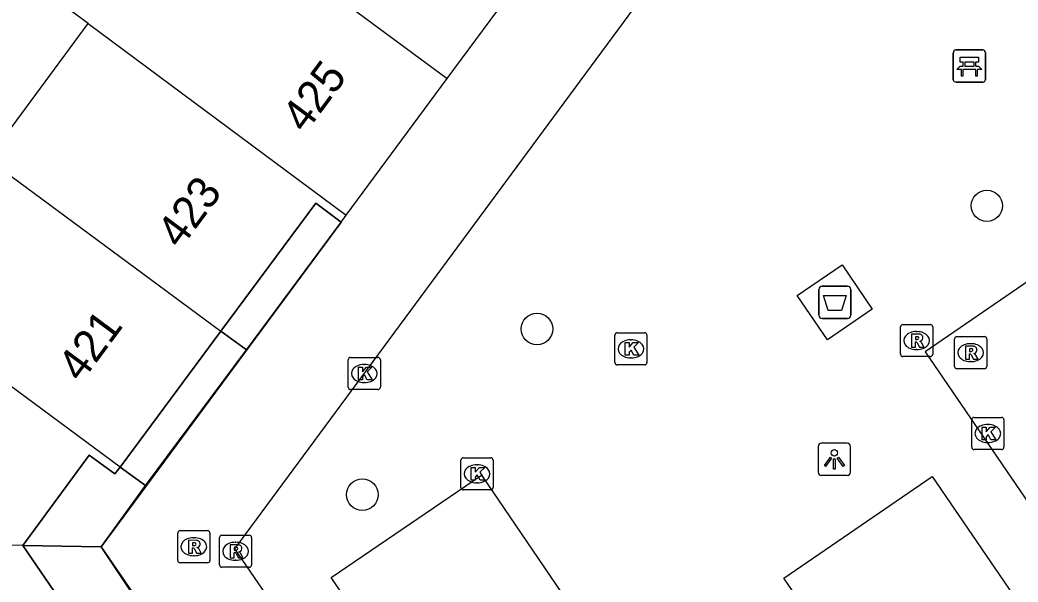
# Model space of a CAD drawing. Extents: x 155275 to 156263, y 382654 to 383635.
# Drawn here: x 155744.26 to 155775.32, y 383229.53 to 383247.02 of the extents above; entities that cross this region are included whole.
import ezdxf

# ---------------------------------------------------------------- set-up
doc = ezdxf.new("R2010")
doc.units = 0
for name, color, linetype in [('IMGEO_Afval_apart_plaats', 7, 'Continuous'), ('IMGEO_Bank', 7, 'Continuous'), ('IMGEO_Boom', 7, 'Continuous'), ('IMGEO_Kolk', 7, 'Continuous'), ('IMGEO_Lichtpunt', 7, 'Continuous'), ('IMGEO_Pand', 7, 'Continuous'), ('IMGEO_Pand_nummerreeks', 7, 'Continuous'), ('IMGEO_Pand_overbouw', 7, 'Continuous'), ('IMGEO_Rijbaan_lokaal_open', 7, 'Continuous'), ('IMGEO_Rioolput', 7, 'Continuous'), ('IMGEO_Voetpad_open', 7, 'Continuous')]:
    doc.layers.add(name, color=color, linetype=linetype)

msp = doc.modelspace()

# ---------------------------------------------------------------- linework, layer by layer
at = {"layer": 'IMGEO_Afval_apart_plaats'}
for p, q in [((155769.227, 383238.731), (155770.017, 383238.731)), ((155770.017, 383238.731), (155769.227, 383238.731)), ((155769.127, 383237.831), (155769.127, 383238.631)), ((155769.127, 383238.631), (155769.127, 383237.831)), ((155770.117, 383238.631), (155770.117, 383237.831)), ((155770.117, 383237.831), (155770.117, 383238.631)), ((155770.017, 383237.731), (155769.227, 383237.731)), ((155769.227, 383237.731), (155770.017, 383237.731))]:
    msp.add_line(p, q, dxfattribs=at)
msp.add_lwpolyline([(155769.27, 383238.445), (155769.974, 383238.445), (155769.825, 383237.975), (155769.419, 383237.975), (155769.27, 383238.445)], dxfattribs=at)
for centre, start, end in [((155769.227, 383238.631), 90, 180), ((155769.227, 383238.631), 90, 180), ((155770.017, 383238.631), 0, 90), ((155770.017, 383238.631), 360, 90), ((155769.227, 383237.831), 180, 270), ((155769.227, 383237.831), 180, 270), ((155770.017, 383237.831), 270, 0), ((155770.017, 383237.831), 270, 0)]:
    msp.add_arc(centre, 0.1, start, end, dxfattribs=at)
at = {"layer": 'IMGEO_Bank'}
for p, q in [((155773.31, 383245.157), (155773.31, 383245.998)), ((155773.31, 383245.998), (155773.31, 383245.157)), ((155773.385, 383246.082), (155774.226, 383246.082)), ((155774.226, 383246.082), (155773.385, 383246.082)), ((155774.31, 383246.007), (155774.31, 383245.166)), ((155774.31, 383245.166), (155774.31, 383246.007)), ((155773.619, 383245.588), (155773.619, 383245.694)), ((155773.663, 383245.694), (155773.663, 383245.588)), ((155773.951, 383245.7), (155773.669, 383245.7)), ((155773.669, 383245.582), (155773.951, 383245.582)), ((155773.957, 383245.588), (155773.957, 383245.694)), ((155774.001, 383245.694), (155774.001, 383245.588)), ((155774.007, 383245.48), (155773.614, 383245.48)), ((155774.235, 383245.082), (155773.394, 383245.082)), ((155773.394, 383245.082), (155774.235, 383245.082))]:
    msp.add_line(p, q, dxfattribs=at)
for points in [[(155773.557, 383245.48), (155773.415, 383245.48), (155773.527, 383245.582), (155773.613, 383245.582)], [(155773.613, 383245.7), (155773.527, 383245.7), (155773.527, 383245.861), (155774.09, 383245.861), (155774.09, 383245.7), (155774.007, 383245.7)], [(155774.007, 383245.582), (155774.09, 383245.582), (155774.202, 383245.48), (155774.063, 383245.48)], [(155773.607, 383245.473), (155773.607, 383245.266), (155773.564, 383245.266), (155773.564, 383245.473)], [(155774.057, 383245.473), (155774.057, 383245.266), (155774.013, 383245.266), (155774.013, 383245.473)]]:
    msp.add_lwpolyline(points, dxfattribs=at)
for centre, radius, start, end in [((155773.388, 383246.004), 0.0779, 92.4484, 184.2845), ((155773.388, 383246.004), 0.0779, 92.4484, 184.2845), ((155774.232, 383246.004), 0.0779, 2.4484, 94.2845), ((155774.232, 383246.004), 0.0779, 2.4484, 94.2845), ((155773.612, 383245.693), 0.00671, 2.8957, 87.1043), ((155773.612, 383245.589), 0.00671, 272.8957, 357.1043), ((155773.669, 383245.693), 0.00671, 92.8957, 177.1043), ((155773.669, 383245.589), 0.00671, 182.8957, 267.1043), ((155773.951, 383245.693), 0.00671, 2.8957, 87.1043), ((155773.951, 383245.589), 0.00671, 272.8957, 357.1043), ((155774.008, 383245.693), 0.00671, 92.8957, 177.1043), ((155774.008, 383245.589), 0.00671, 182.8957, 267.1043), ((155773.557, 383245.473), 0.00671, 2.8957, 87.1043), ((155773.614, 383245.473), 0.00671, 92.8957, 177.1043), ((155774.006, 383245.473), 0.00671, 2.8957, 87.1043), ((155774.063, 383245.473), 0.00671, 92.8957, 177.1043), ((155773.388, 383245.16), 0.0779, 182.4484, 274.2845), ((155773.388, 383245.16), 0.0779, 182.4484, 274.2845), ((155774.232, 383245.16), 0.0779, 272.4484, 4.2845), ((155774.232, 383245.16), 0.0779, 272.4484, 4.2845)]:
    msp.add_arc(centre, radius, start, end, dxfattribs=at)
at = {"layer": 'IMGEO_Boom'}
for centre in [(155774.353, 383241.234), (155760.353, 383237.403), (155754.919, 383232.248)]:
    msp.add_circle(centre, 0.489, dxfattribs=at)
at = {"layer": 'IMGEO_Kolk'}
for p, q in [((155762.775, 383236.358), (155762.775, 383237.21)), ((155762.85, 383237.284), (155763.702, 383237.284)), ((155763.776, 383237.21), (155763.776, 383236.358)), ((155763.263, 383237.064), (155763.288, 383237.064)), ((155754.479, 383235.591), (155754.479, 383236.443)), ((155754.554, 383236.517), (155755.406, 383236.517)), ((155754.967, 383236.297), (155754.992, 383236.297)), ((155755.48, 383236.443), (155755.48, 383235.591)), ((155763.702, 383236.284), (155762.85, 383236.284)), ((155763.286, 383236.504), (155763.261, 383236.504)), ((155754.99, 383235.737), (155754.965, 383235.737)), ((155755.406, 383235.517), (155754.554, 383235.517)), ((155773.883, 383233.725), (155773.883, 383234.577)), ((155773.958, 383234.651), (155774.81, 383234.651)), ((155774.371, 383234.431), (155774.396, 383234.431)), ((155774.884, 383234.577), (155774.884, 383233.725)), ((155774.394, 383233.871), (155774.369, 383233.871)), ((155774.81, 383233.651), (155773.958, 383233.651)), ((155757.988, 383232.471), (155757.988, 383233.323)), ((155758.063, 383233.397), (155758.915, 383233.397)), ((155758.476, 383233.177), (155758.501, 383233.177)), ((155758.989, 383233.323), (155758.989, 383232.471)), ((155758.499, 383232.617), (155758.474, 383232.617)), ((155758.915, 383232.397), (155758.063, 383232.397))]:
    msp.add_line(p, q, dxfattribs=at)
for points in [[(155762.775, 383236.358), (155762.775, 383237.21)], [(155762.85, 383237.284), (155763.702, 383237.284)], [(155763.776, 383237.21), (155763.776, 383236.358)], [(155763.096, 383236.984), (155763.219, 383236.984), (155763.219, 383236.833), (155763.349, 383236.984), (155763.513, 383236.984), (155763.367, 383236.833), (155763.52, 383236.584), (155763.368, 383236.584), (155763.283, 383236.748), (155763.219, 383236.681), (155763.219, 383236.584), (155763.096, 383236.584), (155763.096, 383236.984)], [(155754.479, 383235.591), (155754.479, 383236.443)], [(155754.554, 383236.517), (155755.406, 383236.517)], [(155755.48, 383236.443), (155755.48, 383235.591)], [(155763.702, 383236.284), (155762.85, 383236.284)], [(155754.8, 383236.217), (155754.923, 383236.217), (155754.923, 383236.066), (155755.053, 383236.217), (155755.217, 383236.217), (155755.071, 383236.066), (155755.224, 383235.817), (155755.072, 383235.817), (155754.987, 383235.981), (155754.923, 383235.914), (155754.923, 383235.817), (155754.8, 383235.817), (155754.8, 383236.217)], [(155755.406, 383235.517), (155754.554, 383235.517)], [(155773.883, 383233.725), (155773.883, 383234.577)], [(155773.958, 383234.651), (155774.81, 383234.651)], [(155774.884, 383234.577), (155774.884, 383233.725)], [(155774.204, 383234.351), (155774.327, 383234.351), (155774.327, 383234.2), (155774.457, 383234.351), (155774.621, 383234.351), (155774.475, 383234.2), (155774.628, 383233.951), (155774.476, 383233.951), (155774.391, 383234.115), (155774.327, 383234.048), (155774.327, 383233.951), (155774.204, 383233.951), (155774.204, 383234.351)], [(155774.81, 383233.651), (155773.958, 383233.651)], [(155757.988, 383232.471), (155757.988, 383233.323)], [(155758.063, 383233.397), (155758.915, 383233.397)], [(155758.989, 383233.323), (155758.989, 383232.471)], [(155758.309, 383233.097), (155758.432, 383233.097), (155758.432, 383232.946), (155758.562, 383233.097), (155758.726, 383233.097), (155758.58, 383232.946), (155758.733, 383232.697), (155758.581, 383232.697), (155758.496, 383232.861), (155758.432, 383232.794), (155758.432, 383232.697), (155758.309, 383232.697), (155758.309, 383233.097)], [(155758.915, 383232.397), (155758.063, 383232.397)]]:
    msp.add_lwpolyline(points, dxfattribs=at)
for centre, start, end in [((155762.852, 383237.208), 91.552, 178.448), ((155762.852, 383237.208), 91.552, 178.448), ((155763.7, 383237.208), 1.552, 88.448), ((155763.7, 383237.208), 1.552, 88.448), ((155754.556, 383236.441), 91.552, 178.448), ((155754.556, 383236.441), 91.552, 178.448), ((155755.404, 383236.441), 1.552, 88.448), ((155755.404, 383236.441), 1.552, 88.448), ((155762.852, 383236.36), 181.552, 268.448), ((155762.852, 383236.36), 181.552, 268.448), ((155763.7, 383236.36), 271.552, 358.448), ((155763.7, 383236.36), 271.552, 358.448), ((155754.556, 383235.593), 181.552, 268.448), ((155754.556, 383235.593), 181.552, 268.448), ((155755.404, 383235.593), 271.552, 358.448), ((155755.404, 383235.593), 271.552, 358.448), ((155773.96, 383234.575), 91.552, 178.448), ((155773.96, 383234.575), 91.552, 178.448), ((155774.808, 383234.575), 1.552, 88.448), ((155774.808, 383234.575), 1.552, 88.448), ((155773.96, 383233.727), 181.552, 268.448), ((155773.96, 383233.727), 181.552, 268.448), ((155774.808, 383233.727), 271.552, 358.448), ((155774.808, 383233.727), 271.552, 358.448), ((155758.065, 383233.321), 91.552, 178.448), ((155758.065, 383233.321), 91.552, 178.448), ((155758.913, 383233.321), 1.552, 88.448), ((155758.913, 383233.321), 1.552, 88.448), ((155758.065, 383232.473), 181.552, 268.448), ((155758.065, 383232.473), 181.552, 268.448), ((155758.913, 383232.473), 271.552, 358.448), ((155758.913, 383232.473), 271.552, 358.448)]:
    msp.add_arc(centre, 0.0765, start, end, dxfattribs=at)
for centre, major_axis, ratio, start_param, end_param in [((155763.262, 383236.784), (-0.387, 0.002), 0.722429, 4.712389, 7.853982), ((155763.287, 383236.784), (-0.39, 0.002), 0.717154, 1.570796, 4.712389), ((155754.966, 383236.017), (-0.387, 0.002), 0.722429, 4.712389, 7.853982), ((155754.991, 383236.017), (-0.39, 0.002), 0.717154, 1.570796, 4.712389), ((155774.37, 383234.151), (-0.387, 0.002), 0.722429, 4.712389, 7.853982), ((155774.395, 383234.151), (-0.39, 0.002), 0.717154, 1.570796, 4.712389), ((155758.475, 383232.897), (-0.387, 0.002), 0.722429, 4.712389, 7.853982), ((155758.5, 383232.897), (-0.39, 0.002), 0.717154, 1.570796, 4.712389)]:
    msp.add_ellipse(centre, major_axis=major_axis, ratio=ratio, start_param=start_param, end_param=end_param, dxfattribs=at)
at = {"layer": 'IMGEO_Lichtpunt'}
for p, q in [((155770.011, 383233.846), (155769.203, 383233.846)), ((155770.011, 383233.846), (155769.203, 383233.846)), ((155769.109, 383233.751), (155769.109, 383232.944)), ((155769.109, 383233.751), (155769.109, 383232.944)), ((155770.105, 383232.944), (155770.105, 383233.751)), ((155770.105, 383232.944), (155770.105, 383233.751)), ((155769.203, 383232.85), (155770.011, 383232.85)), ((155769.203, 383232.85), (155770.011, 383232.85))]:
    msp.add_line(p, q, dxfattribs=at)
for points in [[(155769.483, 383233.415), (155769.522, 383233.387), (155769.334, 383233.125), (155769.296, 383233.152), (155769.483, 383233.415)], [(155769.585, 383233.367), (155769.632, 383233.367), (155769.632, 383233.045), (155769.585, 383233.045), (155769.585, 383233.367)], [(155769.695, 383233.387), (155769.733, 383233.414), (155769.92, 383233.152), (155769.881, 383233.124), (155769.695, 383233.387)]]:
    msp.add_lwpolyline(points, dxfattribs=at)
msp.add_circle((155769.608, 383233.549), 0.0994, dxfattribs=at)
for centre, start, end in [((155769.203, 383233.751), 90, 180), ((155769.203, 383233.751), 90, 180), ((155770.011, 383233.751), 0, 90), ((155770.011, 383233.751), 0, 90), ((155769.203, 383232.944), 180, 270), ((155769.203, 383232.944), 180, 270), ((155770.011, 383232.944), 270, 0), ((155770.011, 383232.944), 270, 360)]:
    msp.add_arc(centre, 0.0946, start, end, dxfattribs=at)
at = {"layer": 'IMGEO_Pand'}
for points in [[(155746.382, 383246.906), (155744.774, 383248.095), (155747.906, 383252.331)], [(155747.906, 383252.331), (155757.559, 383245.193)], [(155757.559, 383245.193), (155760.679, 383249.411)], [(155743.261, 383242.688), (155746.382, 383246.906)], [(155746.382, 383246.906), (155754.416, 383240.942)], [(155754.416, 383240.942), (155757.559, 383245.193)], [(155743.261, 383242.688), (155750.514, 383237.331)], [(155750.514, 383237.331), (155753.47, 383241.315), (155754.259, 383240.73)], [(155754.259, 383240.73), (155754.416, 383240.942)], [(155747.379, 383233.106), (155740.14, 383238.453)], [(155747.379, 383233.106), (155750.514, 383237.331)], [(155744.353, 383230.665), (155746.421, 383233.476), (155747.22, 383232.892), (155747.379, 383233.106)], [(155744.353, 383230.665), (155734.527, 383230.848)], [(155746.309, 383227.814), (155744.353, 383230.665)]]:
    msp.add_lwpolyline(points, dxfattribs=at)
at = {"layer": 'IMGEO_Pand_overbouw'}
for points in [[(155750.514, 383237.331), (155751.317, 383236.754), (155754.259, 383240.73), (155753.47, 383241.315)], [(155747.379, 383233.106), (155748.168, 383232.533), (155751.317, 383236.754), (155750.514, 383237.331)], [(155747.379, 383233.106), (155747.22, 383232.892), (155746.421, 383233.476), (155744.353, 383230.665), (155746.794, 383230.63), (155748.168, 383232.533)], [(155744.353, 383230.665), (155746.309, 383227.814), (155747.124, 383228.378), (155747.911, 383228.944), (155746.794, 383230.63)]]:
    msp.add_lwpolyline(points, close=True, dxfattribs=at)
at = {"layer": 'IMGEO_Rijbaan_lokaal_open'}
for points in [[(155817.087, 383320.059), (155811.131, 383312.082), (155798.256, 383294.644), (155789.533, 383282.828), (155777.762, 383266.885), (155770.477, 383257.018), (155750.942, 383230.559), (155753.136, 383227.355), (155767.095, 383206.967), (155771.224, 383200.936), (155773.915, 383197.049), (155790.895, 383199.943), (155792.328, 383200.159), (155792.43, 383196.787)], [(155843.488, 383208.615), (155827.482, 383232.012), (155821.26, 383241.107), (155811.353, 383255.588), (155807.738, 383260.872), (155793.514, 383251.129), (155783.237, 383244.091), (155772.43, 383236.689), (155786.907, 383215.526), (155798.734, 383198.236)], [(155769.848, 383239.395), (155770.789, 383238.022), (155769.395, 383237.067), (155768.454, 383238.44), (155769.848, 383239.395)], [(155757.012, 383225.183), (155753.953, 383229.671), (155758.629, 383232.86), (155771.212, 383214.353)], [(155783.949, 383216.297), (155779.333, 383213.139), (155768.037, 383229.651), (155772.653, 383232.81), (155783.949, 383216.297)]]:
    msp.add_lwpolyline(points, dxfattribs=at)
at = {"layer": 'IMGEO_Rioolput'}
for p, q in [((155771.742, 383237.542), (155772.594, 383237.542)), ((155771.667, 383236.616), (155771.667, 383237.468)), ((155772.155, 383237.322), (155772.18, 383237.322)), ((155772.668, 383237.468), (155772.668, 383236.616)), ((155773.349, 383236.24), (155773.349, 383237.092)), ((155773.424, 383237.166), (155774.276, 383237.166)), ((155773.837, 383236.946), (155773.862, 383236.946)), ((155774.35, 383237.092), (155774.35, 383236.24)), ((155772.178, 383236.762), (155772.153, 383236.762)), ((155772.594, 383236.542), (155771.742, 383236.542)), ((155773.86, 383236.386), (155773.835, 383236.386)), ((155774.276, 383236.166), (155773.424, 383236.166)), ((155749.173, 383230.203), (155749.173, 383231.055)), ((155749.248, 383231.129), (155750.1, 383231.129)), ((155750.174, 383231.055), (155750.174, 383230.203)), ((155750.548, 383230.988), (155751.4, 383230.988)), ((155749.661, 383230.909), (155749.686, 383230.909)), ((155750.473, 383230.062), (155750.473, 383230.914)), ((155750.961, 383230.768), (155750.986, 383230.768)), ((155751.474, 383230.914), (155751.474, 383230.062)), ((155749.684, 383230.349), (155749.659, 383230.349)), ((155750.1, 383230.129), (155749.248, 383230.129)), ((155750.984, 383230.208), (155750.959, 383230.208)), ((155751.4, 383229.988), (155750.548, 383229.988))]:
    msp.add_line(p, q, dxfattribs=at)
for points in [[(155771.742, 383237.542), (155772.594, 383237.542)], [(155771.667, 383236.616), (155771.667, 383237.468)], [(155772.256, 383237.24), (155772.004, 383237.242), (155772.004, 383236.842)], [(155772.668, 383237.468), (155772.668, 383236.616)], [(155772.004, 383236.842), (155772.128, 383236.842), (155772.128, 383237.004), (155772.139, 383237.004)], [(155772.182, 383237.161), (155772.128, 383237.161), (155772.128, 383237.08)], [(155772.128, 383237.08), (155772.18, 383237.08)], [(155772.186, 383236.975), (155772.257, 383236.842), (155772.397, 383236.842), (155772.332, 383236.968)], [(155773.349, 383236.24), (155773.349, 383237.092)], [(155773.424, 383237.166), (155774.276, 383237.166)], [(155773.938, 383236.864), (155773.686, 383236.866), (155773.686, 383236.466)], [(155774.35, 383237.092), (155774.35, 383236.24)], [(155773.686, 383236.466), (155773.81, 383236.466), (155773.81, 383236.628), (155773.821, 383236.628)], [(155773.864, 383236.785), (155773.81, 383236.785), (155773.81, 383236.704)], [(155773.81, 383236.704), (155773.862, 383236.704)], [(155773.868, 383236.599), (155773.939, 383236.466), (155774.079, 383236.466), (155774.014, 383236.592)], [(155772.594, 383236.542), (155771.742, 383236.542)], [(155774.276, 383236.166), (155773.424, 383236.166)], [(155749.173, 383230.203), (155749.173, 383231.055)], [(155749.248, 383231.129), (155750.1, 383231.129)], [(155750.174, 383231.055), (155750.174, 383230.203)], [(155750.548, 383230.988), (155751.4, 383230.988)], [(155749.762, 383230.827), (155749.51, 383230.829), (155749.51, 383230.429)], [(155749.688, 383230.748), (155749.634, 383230.748), (155749.634, 383230.667)], [(155749.634, 383230.667), (155749.686, 383230.667)], [(155750.473, 383230.062), (155750.473, 383230.914)], [(155751.062, 383230.686), (155750.81, 383230.688), (155750.81, 383230.288)], [(155751.474, 383230.914), (155751.474, 383230.062)], [(155749.51, 383230.429), (155749.634, 383230.429), (155749.634, 383230.591), (155749.645, 383230.591)], [(155749.692, 383230.562), (155749.763, 383230.429), (155749.903, 383230.429), (155749.838, 383230.555)], [(155750.81, 383230.288), (155750.934, 383230.288), (155750.934, 383230.45), (155750.945, 383230.45)], [(155750.988, 383230.607), (155750.934, 383230.607), (155750.934, 383230.526)], [(155750.934, 383230.526), (155750.986, 383230.526)], [(155750.992, 383230.421), (155751.063, 383230.288), (155751.203, 383230.288), (155751.138, 383230.414)], [(155750.1, 383230.129), (155749.248, 383230.129)], [(155751.4, 383229.988), (155750.548, 383229.988)]]:
    msp.add_lwpolyline(points, dxfattribs=at)
for centre, radius, start, end in [((155771.744, 383237.466), 0.0765, 91.552, 178.448), ((155771.744, 383237.466), 0.0765, 91.552, 178.448), ((155772.592, 383237.466), 0.0765, 1.552, 88.448), ((155772.592, 383237.466), 0.0765, 1.552, 88.448), ((155772.255, 383237.13), 0.109, 350.3612, 89.416), ((155772.138, 383236.951), 0.0533, 26.0293, 88.6989), ((155772.164, 383237.269), 0.19, 274.7715, 282.9687), ((155772.188, 383237.065), 0.0964, 77.0061, 93.1865), ((155772.202, 383237.122), 0.0378, 276.6634, 79.6772), ((155772.253, 383237.13), 0.112, 277.5842, 350.9817), ((155772.237, 383236.915), 0.108, 29.5134, 73.7905), ((155773.426, 383237.09), 0.0765, 91.552, 178.448), ((155773.426, 383237.09), 0.0765, 91.552, 178.448), ((155773.937, 383236.754), 0.109, 350.3612, 89.416), ((155774.274, 383237.09), 0.0765, 1.552, 88.448), ((155774.274, 383237.09), 0.0765, 1.552, 88.448), ((155771.744, 383236.618), 0.0765, 181.552, 268.448), ((155771.744, 383236.618), 0.0765, 181.552, 268.448), ((155772.592, 383236.618), 0.0765, 271.552, 358.448), ((155772.592, 383236.618), 0.0765, 271.552, 358.448), ((155773.82, 383236.575), 0.0533, 26.0293, 88.6989), ((155773.846, 383236.893), 0.19, 274.7715, 282.9687), ((155773.87, 383236.689), 0.0964, 77.0061, 93.1865), ((155773.884, 383236.746), 0.0378, 276.6634, 79.6772), ((155773.935, 383236.754), 0.112, 277.5842, 350.9817), ((155773.919, 383236.539), 0.108, 29.5134, 73.7905), ((155773.426, 383236.242), 0.0765, 181.552, 268.448), ((155773.426, 383236.242), 0.0765, 181.552, 268.448), ((155774.274, 383236.242), 0.0765, 271.552, 358.448), ((155774.274, 383236.242), 0.0765, 271.552, 358.448), ((155749.25, 383231.053), 0.0765, 91.552, 178.448), ((155749.25, 383231.053), 0.0765, 91.552, 178.448), ((155750.098, 383231.053), 0.0765, 1.552, 88.448), ((155750.098, 383231.053), 0.0765, 1.552, 88.448), ((155750.55, 383230.912), 0.0765, 91.552, 178.448), ((155750.55, 383230.912), 0.0765, 91.552, 178.448), ((155751.398, 383230.912), 0.0765, 1.552, 88.448), ((155751.398, 383230.912), 0.0765, 1.552, 88.448), ((155749.67, 383230.856), 0.19, 274.7715, 282.9687), ((155749.694, 383230.652), 0.0964, 77.0061, 93.1865), ((155749.708, 383230.709), 0.0378, 276.6634, 79.6772), ((155749.761, 383230.717), 0.109, 350.3612, 89.416), ((155749.759, 383230.717), 0.112, 277.5842, 350.9817), ((155751.061, 383230.576), 0.109, 350.3612, 89.416), ((155749.644, 383230.538), 0.0533, 26.0293, 88.6989), ((155749.743, 383230.502), 0.108, 29.5134, 73.7905), ((155750.944, 383230.397), 0.0533, 26.0293, 88.6989), ((155750.97, 383230.715), 0.19, 274.7715, 282.9687), ((155750.994, 383230.511), 0.0964, 77.0061, 93.1865), ((155751.008, 383230.568), 0.0378, 276.6634, 79.6772), ((155751.059, 383230.576), 0.112, 277.5842, 350.9817), ((155751.043, 383230.361), 0.108, 29.5134, 73.7905), ((155749.25, 383230.205), 0.0765, 181.552, 268.448), ((155749.25, 383230.205), 0.0765, 181.552, 268.448), ((155750.098, 383230.205), 0.0765, 271.552, 358.448), ((155750.098, 383230.205), 0.0765, 271.552, 358.448), ((155750.55, 383230.064), 0.0765, 181.552, 268.448), ((155750.55, 383230.064), 0.0765, 181.552, 268.448), ((155751.398, 383230.064), 0.0765, 271.552, 358.448), ((155751.398, 383230.064), 0.0765, 271.552, 358.448)]:
    msp.add_arc(centre, radius, start, end, dxfattribs=at)
for centre, major_axis, ratio, start_param, end_param in [((155772.154, 383237.042), (-0.387, 0.002), 0.722429, 4.712389, 7.853982), ((155772.179, 383237.042), (-0.39, 0.002), 0.717154, 1.570796, 4.712389), ((155773.836, 383236.666), (-0.387, 0.002), 0.722429, 4.712389, 7.853982), ((155773.861, 383236.666), (-0.39, 0.002), 0.717154, 1.570796, 4.712389), ((155749.66, 383230.629), (-0.387, 0.002), 0.722429, 4.712389, 7.853982), ((155749.685, 383230.629), (-0.39, 0.002), 0.717154, 1.570796, 4.712389), ((155750.96, 383230.488), (-0.387, 0.002), 0.722429, 4.712389, 7.853982), ((155750.985, 383230.488), (-0.39, 0.002), 0.717154, 1.570796, 4.712389)]:
    msp.add_ellipse(centre, major_axis=major_axis, ratio=ratio, start_param=start_param, end_param=end_param, dxfattribs=at)
at = {"layer": 'IMGEO_Voetpad_open'}
msp.add_lwpolyline([(155754.259, 383240.73), (155746.794, 383230.63), (155750.925, 383224.614)], dxfattribs=at)

# ---------------------------------------------------------------- texts
at = {"layer": 'IMGEO_Pand_nummerreeks'}
for s, rotation, p in [('425', 53.5156, (155753.144, 383243.46)), ('423', 53.4269, (155749.255, 383239.863)), ('421', 53.4269, (155746.169, 383235.704))]:
    msp.add_text(s, height=1, rotation=rotation, dxfattribs=at).set_placement(p)

doc.saveas('drawing.dxf')
